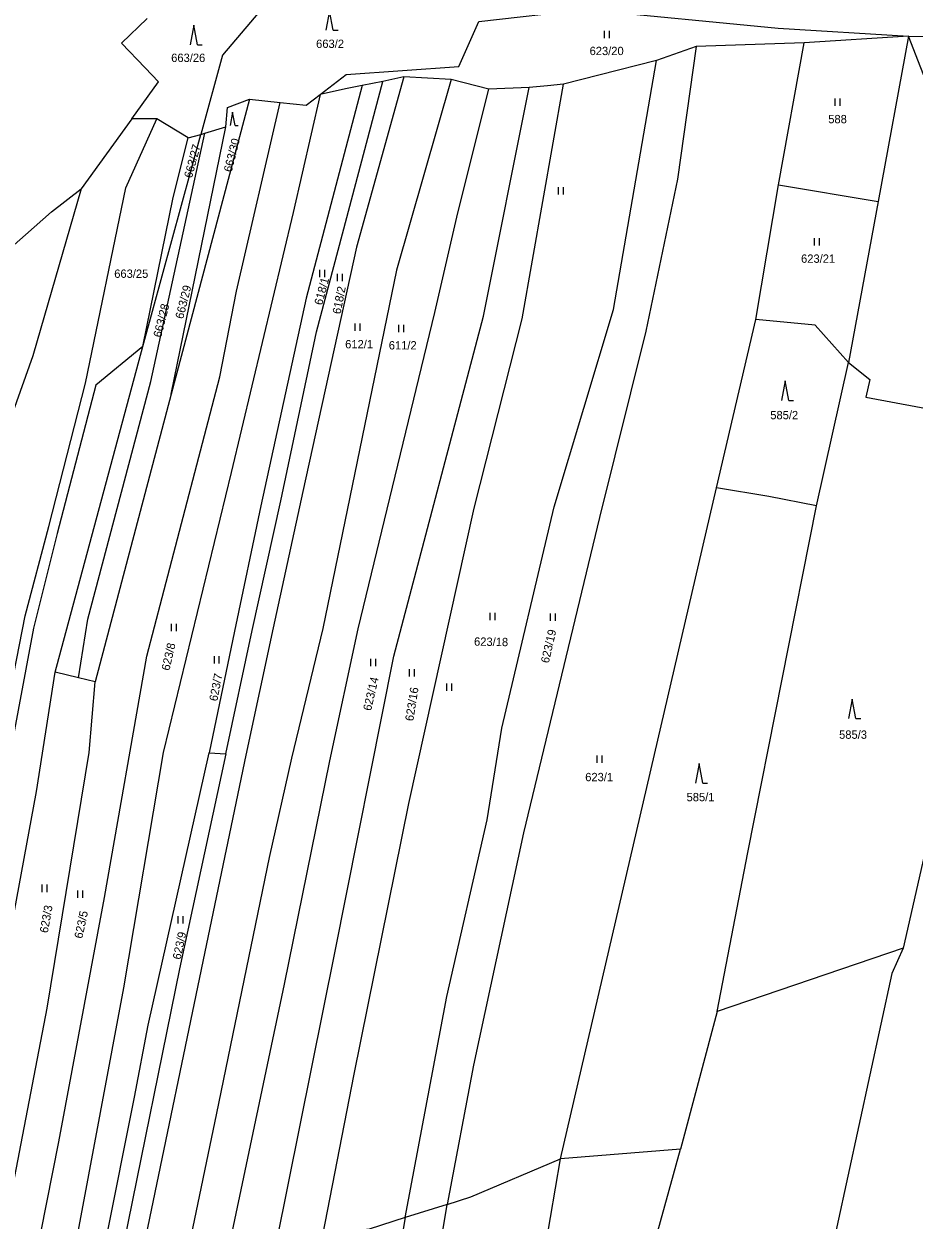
# Model space of a CAD drawing. Extents: x -755528 to -748832, y -1118122 to -1111095.
# Drawn here: x -753456.7 to -753275.1, y -1113610.9 to -1113366.7 of the extents above; entities that cross this region are included whole.
import ezdxf

# ---------------------------------------------------------------- set-up
doc = ezdxf.new("R2010")
doc.units = 0
for name, color, linetype in [('DZ_DO_PUPFL', 7, 'Continuous'), ('DZ_NAD_PUPFL', 7, 'Continuous'), ('DZ_NAD_ZPF', 7, 'Continuous'), ('TZ_UMVŽST', 7, 'Continuous')]:
    doc.layers.add(name, color=color, linetype=linetype)

msp = doc.modelspace()

# ---------------------------------------------------------------- linework, layer by layer
at = {"layer": 'DZ_NAD_PUPFL'}
for p, q in [((-753436.84, -1113370.67), (-753431.57, -1113365.62)), ((-753432.01, -1113375.71), (-753436.84, -1113370.67)), ((-753434.71, -1113386.08), (-753445.06, -1113400.41))]:
    msp.add_line(p, q, dxfattribs=at)
for points in [[(-753434.71, -1113386.08), (-753429.28, -1113378.55), (-753432.01, -1113375.71)], [(-753462.93, -1113415.5), (-753451.15, -1113405.09), (-753445.06, -1113400.41)]]:
    msp.add_lwpolyline(points, dxfattribs=at)
at = {"layer": 'DZ_NAD_ZPF'}
for p, q in [((-753276.25, -1113369.24), (-753297.53, -1113370.57)), ((-753276.25, -1113369.24), (-753282.46, -1113402.98)), ((-753276.25, -1113369.24), (-753271.7, -1113369.3)), ((-753319.55, -1113371.35), (-753327.68, -1113374.19)), ((-753297.53, -1113370.57), (-753319.55, -1113371.35)), ((-753302.79, -1113399.57), (-753297.53, -1113370.57)), ((-753383.51, -1113378.47), (-753387.72, -1113379.33)), ((-753379.21, -1113377.55), (-753383.51, -1113378.47)), ((-753369.55, -1113378.06), (-753379.21, -1113377.55)), ((-753361.87, -1113380.08), (-753369.55, -1113378.06)), ((-753353.68, -1113379.73), (-753361.87, -1113380.08)), ((-753410.73, -1113382.1), (-753426.68, -1113442.3)), ((-753410.73, -1113382.1), (-753404.49, -1113382.76)), ((-753429.66, -1113386.14), (-753434.71, -1113386.08)), ((-753423.25, -1113390.01), (-753429.66, -1113386.14)), ((-753426.68, -1113442.3), (-753415.58, -1113387.75)), ((-753419.85, -1113389.06), (-753415.58, -1113387.75)), ((-753432.5, -1113432.56), (-753420.65, -1113389.28)), ((-753423.25, -1113390.01), (-753420.65, -1113389.28)), ((-753420.65, -1113389.28), (-753419.85, -1113389.06)), ((-753307.44, -1113427.06), (-753302.79, -1113399.57)), ((-753302.79, -1113399.57), (-753282.46, -1113402.98)), ((-753282.46, -1113402.98), (-753288.5, -1113435.81)), ((-753315.42, -1113461.41), (-753307.44, -1113427.06)), ((-753450.39, -1113499.01), (-753432.5, -1113432.56)), ((-753295.05, -1113465.08), (-753288.5, -1113435.81)), ((-753426.68, -1113442.3), (-753442.23, -1113501.01)), ((-753253.28, -1113448.8), (-753277.32, -1113555.35)), ((-753347.25, -1113598.36), (-753315.42, -1113461.41)), ((-753445.63, -1113500.18), (-753450.39, -1113499.01)), ((-753442.23, -1113501.01), (-753445.63, -1113500.18)), ((-753418.94, -1113515.53), (-753415.52, -1113515.71)), ((-753277.32, -1113555.35), (-753315.27, -1113568.29)), ((-753315.27, -1113568.29), (-753322.8, -1113596.39)), ((-753322.8, -1113596.39), (-753347.25, -1113598.36)), ((-753330.86, -1113625.62), (-753322.8, -1113596.39)), ((-753352.23, -1113627.25), (-753347.25, -1113598.36)), ((-753370.37, -1113607.65), (-753378.95, -1113610.36)), ((-753373.99, -1113629.03), (-753370.37, -1113607.65)), ((-753378.95, -1113610.36), (-753385.25, -1113645.8))]:
    msp.add_line(p, q, dxfattribs=at)
for points in [[(-753406.72, -1113361.91), (-753416.23, -1113373.14), (-753420.65, -1113389.28)], [(-753363.92, -1113366.23), (-753342.23, -1113363.82), (-753302.87, -1113367.57), (-753276.25, -1113369.24)], [(-753396.29, -1113381.11), (-753390.98, -1113377.03), (-753368.04, -1113375.41), (-753363.92, -1113366.23)], [(-753250.45, -1113436.16), (-753251.74, -1113432.33), (-753276.25, -1113369.24)], [(-753319.55, -1113371.35), (-753323.37, -1113398.45), (-753329.82, -1113429.41), (-753339.28, -1113467.44), (-753354.84, -1113531.81), (-753365.01, -1113579.21), (-753370.37, -1113607.65)], [(-753378.95, -1113610.36), (-753370.48, -1113565.22), (-753362.23, -1113529.16), (-753359.22, -1113510.48), (-753348.56, -1113465.29), (-753336.43, -1113425.01), (-753327.68, -1113374.19)], [(-753327.68, -1113374.19), (-753339.42, -1113377.18), (-753346.66, -1113379)], [(-753379.21, -1113377.55), (-753388.89, -1113412.31), (-753399.81, -1113462.19), (-753405.91, -1113489.96), (-753411.49, -1113516), (-753419.51, -1113554.46), (-753432.22, -1113615.73)], [(-753369.55, -1113378.06), (-753380.72, -1113416.97), (-753395.78, -1113490.14), (-753402.15, -1113516.59), (-753406.72, -1113536.86), (-753417.42, -1113589.01), (-753423.01, -1113615.87)], [(-753415.52, -1113515.71), (-753410.2, -1113490.56), (-753404.36, -1113464.09), (-753397.03, -1113429.59), (-753391.77, -1113409.6), (-753383.51, -1113378.47)], [(-753395.75, -1113613.91), (-753389.38, -1113581.06), (-753378.21, -1113525.82), (-753364.88, -1113465.57), (-753355.11, -1113426.95), (-753346.66, -1113379)], [(-753346.66, -1113379), (-753349.93, -1113379.4), (-753353.68, -1113379.73)], [(-753396.29, -1113381.11), (-753401.82, -1113405.19), (-753414.46, -1113458.31), (-753428.33, -1113515.44), (-753436.45, -1113563.44), (-753445.96, -1113614.35)], [(-753387.72, -1113379.33), (-753399.17, -1113422.72), (-753408.39, -1113465.07), (-753413.78, -1113490.68), (-753418.94, -1113515.53)], [(-753414.83, -1113615.99), (-753403.58, -1113562.7), (-753394.35, -1113517.11), (-753388.53, -1113490.21), (-753372.9, -1113425.64), (-753368.18, -1113405.3), (-753361.87, -1113380.08)], [(-753405.16, -1113615.14), (-753393.33, -1113556.29), (-753381.26, -1113495.77), (-753362.97, -1113426.37), (-753353.68, -1113379.73)], [(-753404.49, -1113382.76), (-753399.18, -1113383.33), (-753396.29, -1113381.11)], [(-753387.72, -1113379.33), (-753391.1, -1113379.98), (-753396.29, -1113381.11)], [(-753453.29, -1113613.47), (-753449.61, -1113594.86), (-753440.32, -1113545.04), (-753431.67, -1113495.79), (-753428.53, -1113483.8), (-753416.8, -1113438.79), (-753413.34, -1113421.28), (-753404.49, -1113382.76)], [(-753415.58, -1113387.75), (-753415.2, -1113383.77), (-753410.73, -1113382.1)], [(-753473.9, -1113579.49), (-753468.67, -1113549.51), (-753456.49, -1113487.55), (-753451.63, -1113469.3), (-753444.17, -1113440.05), (-753435.98, -1113400.2), (-753429.66, -1113386.14)], [(-753445.63, -1113500.18), (-753443.68, -1113488.22), (-753430.85, -1113439.7), (-753419.85, -1113389.06)], [(-753432.5, -1113432.56), (-753426.31, -1113402.14), (-753423.25, -1113390.01)], [(-753445.06, -1113400.41), (-753454.95, -1113434.48), (-753462.38, -1113455.39), (-753469.18, -1113480.66), (-753477.3, -1113537.8), (-753485.21, -1113577.4)], [(-753288.5, -1113435.81), (-753295.32, -1113428.21), (-753307.44, -1113427.06)], [(-753432.5, -1113432.56), (-753442.08, -1113440.47), (-753449.95, -1113470.73), (-753454.76, -1113490.04), (-753471.63, -1113579.91)], [(-753288.5, -1113435.81), (-753284.15, -1113439.32), (-753284.96, -1113442.88), (-753253.28, -1113448.8)], [(-753295.05, -1113465.08), (-753304.76, -1113463.18), (-753315.42, -1113461.41)], [(-753315.27, -1113568.29), (-753309.06, -1113535.83), (-753295.05, -1113465.08)], [(-753502.88, -1113771.27), (-753494.9, -1113739.14), (-753479.17, -1113679.31), (-753481.55, -1113674.49), (-753475.44, -1113637.71), (-753470.43, -1113611.4), (-753462.26, -1113567.02), (-753454.18, -1113523.38), (-753450.39, -1113499.01)], [(-753496.72, -1113781.33), (-753487.53, -1113743.31), (-753477.31, -1113701.87), (-753471.32, -1113676.12), (-753472.32, -1113672.61), (-753468.39, -1113649.95), (-753460.66, -1113612.58), (-753452.03, -1113567.63), (-753443.46, -1113515.43), (-753442.23, -1113501.01)], [(-753449.97, -1113668.67), (-753444.36, -1113637.15), (-753440.03, -1113615.07), (-753434.19, -1113585.77), (-753431.4, -1113571.08), (-753418.94, -1113515.53)], [(-753415.52, -1113515.71), (-753425, -1113559.61), (-753436.39, -1113615.51), (-753441.57, -1113639.59), (-753446.53, -1113668.47)], [(-753277.32, -1113555.35), (-753279.66, -1113560.55), (-753290.85, -1113612.2), (-753295.95, -1113640.82)], [(-753370.37, -1113607.65), (-753365.57, -1113606.14), (-753347.25, -1113598.36)], [(-753378.95, -1113610.36), (-753386.3, -1113612.68), (-753395.75, -1113613.91)]]:
    msp.add_lwpolyline(points, dxfattribs=at)
at = {"layer": 'TZ_UMVŽST'}
for p, q in [((-753394.4, -1113364.04), (-753395.15, -1113368.04)), ((-753393.65, -1113368.04), (-753394.4, -1113364.04)), ((-753422.11, -1113367), (-753422.86, -1113371)), ((-753421.36, -1113371), (-753422.11, -1113367)), ((-753393.65, -1113368.04), (-753392.654, -1113368.04)), ((-753338.261, -1113369.66), (-753338.261, -1113368.16)), ((-753337.26, -1113369.66), (-753337.26, -1113368.16)), ((-753421.36, -1113371), (-753420.364, -1113371)), ((-753291.231, -1113383.46), (-753291.231, -1113381.96)), ((-753290.23, -1113383.46), (-753290.23, -1113381.96)), ((-753414.18, -1113384.76), (-753414.682, -1113387.44)), ((-753413.678, -1113387.44), (-753414.18, -1113384.76)), ((-753413.678, -1113387.44), (-753413.01, -1113387.44)), ((-753347.671, -1113401.56), (-753347.671, -1113400.06)), ((-753346.67, -1113401.56), (-753346.67, -1113400.06)), ((-753295.441, -1113411.93), (-753295.441, -1113410.43)), ((-753294.44, -1113411.93), (-753294.44, -1113410.43)), ((-753396.381, -1113418.44), (-753396.381, -1113416.94)), ((-753395.38, -1113418.44), (-753395.38, -1113416.94)), ((-753392.761, -1113419.25), (-753392.761, -1113417.75)), ((-753391.76, -1113419.25), (-753391.76, -1113417.75)), ((-753389.131, -1113429.4), (-753389.131, -1113427.9)), ((-753388.13, -1113429.4), (-753388.13, -1113427.9)), ((-753380.231, -1113429.63), (-753380.231, -1113428.13)), ((-753379.23, -1113429.63), (-753379.23, -1113428.13)), ((-753301.44, -1113439.59), (-753302.19, -1113443.59)), ((-753300.69, -1113443.59), (-753301.44, -1113439.59)), ((-753300.69, -1113443.59), (-753299.694, -1113443.59)), ((-753361.591, -1113488.4), (-753361.591, -1113486.9)), ((-753360.59, -1113488.4), (-753360.59, -1113486.9)), ((-753349.311, -1113488.56), (-753349.311, -1113487.06)), ((-753348.31, -1113488.56), (-753348.31, -1113487.06)), ((-753426.621, -1113490.7), (-753426.621, -1113489.2)), ((-753425.62, -1113490.7), (-753425.62, -1113489.2)), ((-753417.881, -1113497.27), (-753417.881, -1113495.77)), ((-753416.88, -1113497.27), (-753416.88, -1113495.77)), ((-753385.971, -1113497.81), (-753385.971, -1113496.31)), ((-753384.97, -1113497.81), (-753384.97, -1113496.31)), ((-753378.061, -1113499.94), (-753378.061, -1113498.44)), ((-753377.06, -1113499.94), (-753377.06, -1113498.44)), ((-753370.471, -1113502.87), (-753370.471, -1113501.37)), ((-753369.47, -1113502.87), (-753369.47, -1113501.37)), ((-753287.73, -1113504.52), (-753288.48, -1113508.52)), ((-753286.98, -1113508.52), (-753287.73, -1113504.52)), ((-753286.98, -1113508.52), (-753285.984, -1113508.52)), ((-753339.771, -1113517.53), (-753339.771, -1113516.03)), ((-753338.77, -1113517.53), (-753338.77, -1113516.03)), ((-753318.99, -1113517.69), (-753319.74, -1113521.69)), ((-753318.24, -1113521.69), (-753318.99, -1113517.69)), ((-753318.24, -1113521.69), (-753317.244, -1113521.69)), ((-753453.021, -1113543.9), (-753453.021, -1113542.4)), ((-753452.02, -1113543.9), (-753452.02, -1113542.4)), ((-753445.741, -1113545.1), (-753445.741, -1113543.6)), ((-753444.74, -1113545.1), (-753444.74, -1113543.6)), ((-753425.241, -1113550.35), (-753425.241, -1113548.85)), ((-753424.24, -1113550.35), (-753424.24, -1113548.85))]:
    msp.add_line(p, q, dxfattribs=at)

# ---------------------------------------------------------------- texts
at = {"layer": 'DZ_DO_PUPFL'}
for s, p in [('663/2', (-753397.13, -1113371.64)), ('623/20', (-753341.33, -1113373.1)), ('663/26', (-753426.7, -1113374.5)), ('588', (-753292.63, -1113387.01)), ('623/21', (-753298.18, -1113415.49)), ('663/25', (-753438.32, -1113418.56)), ('612/1', (-753391.2, -1113432.95)), ('611/2', (-753382.3, -1113433.18)), ('585/2', (-753304.46, -1113447.42)), ('585/3', (-753290.42, -1113512.63)), ('623/1', (-753342.22, -1113521.29)), ('585/1', (-753321.54, -1113525.38))]:
    msp.add_text(s, height=1.7, dxfattribs=at).set_placement(p)
for s, rotation, p in [('663/27', 75, (-753422.468, -1113398.319)), ('663/30', 76, (-753414.365, -1113397.095)), ('663/29', 76, (-753424.245, -1113427.055)), ('618/1', 75, (-753395.908, -1113424.249)), ('618/2', 79, (-753392.155, -1113426.062)), ('663/28', 76, (-753428.745, -1113430.835)), ('623/19', 77, (-753349.661, -1113497.311)), ('623/8', 77, (-753427.071, -1113498.821)), ('623/18', 359, (-753364.914, -1113493.619)), ('623/7', 79, (-753417.305, -1113505.062)), ('623/14', 77, (-753385.921, -1113507.031)), ('623/16', 81, (-753377.31, -1113509.112)), ('623/3', 80, (-753451.872, -1113552.357)), ('623/5', 78, (-753444.838, -1113553.506)), ('623/9', 78, (-753424.778, -1113557.796))]:
    msp.add_text(s, height=1.7, rotation=rotation, dxfattribs=at).set_placement(p)

doc.saveas('drawing.dxf')
